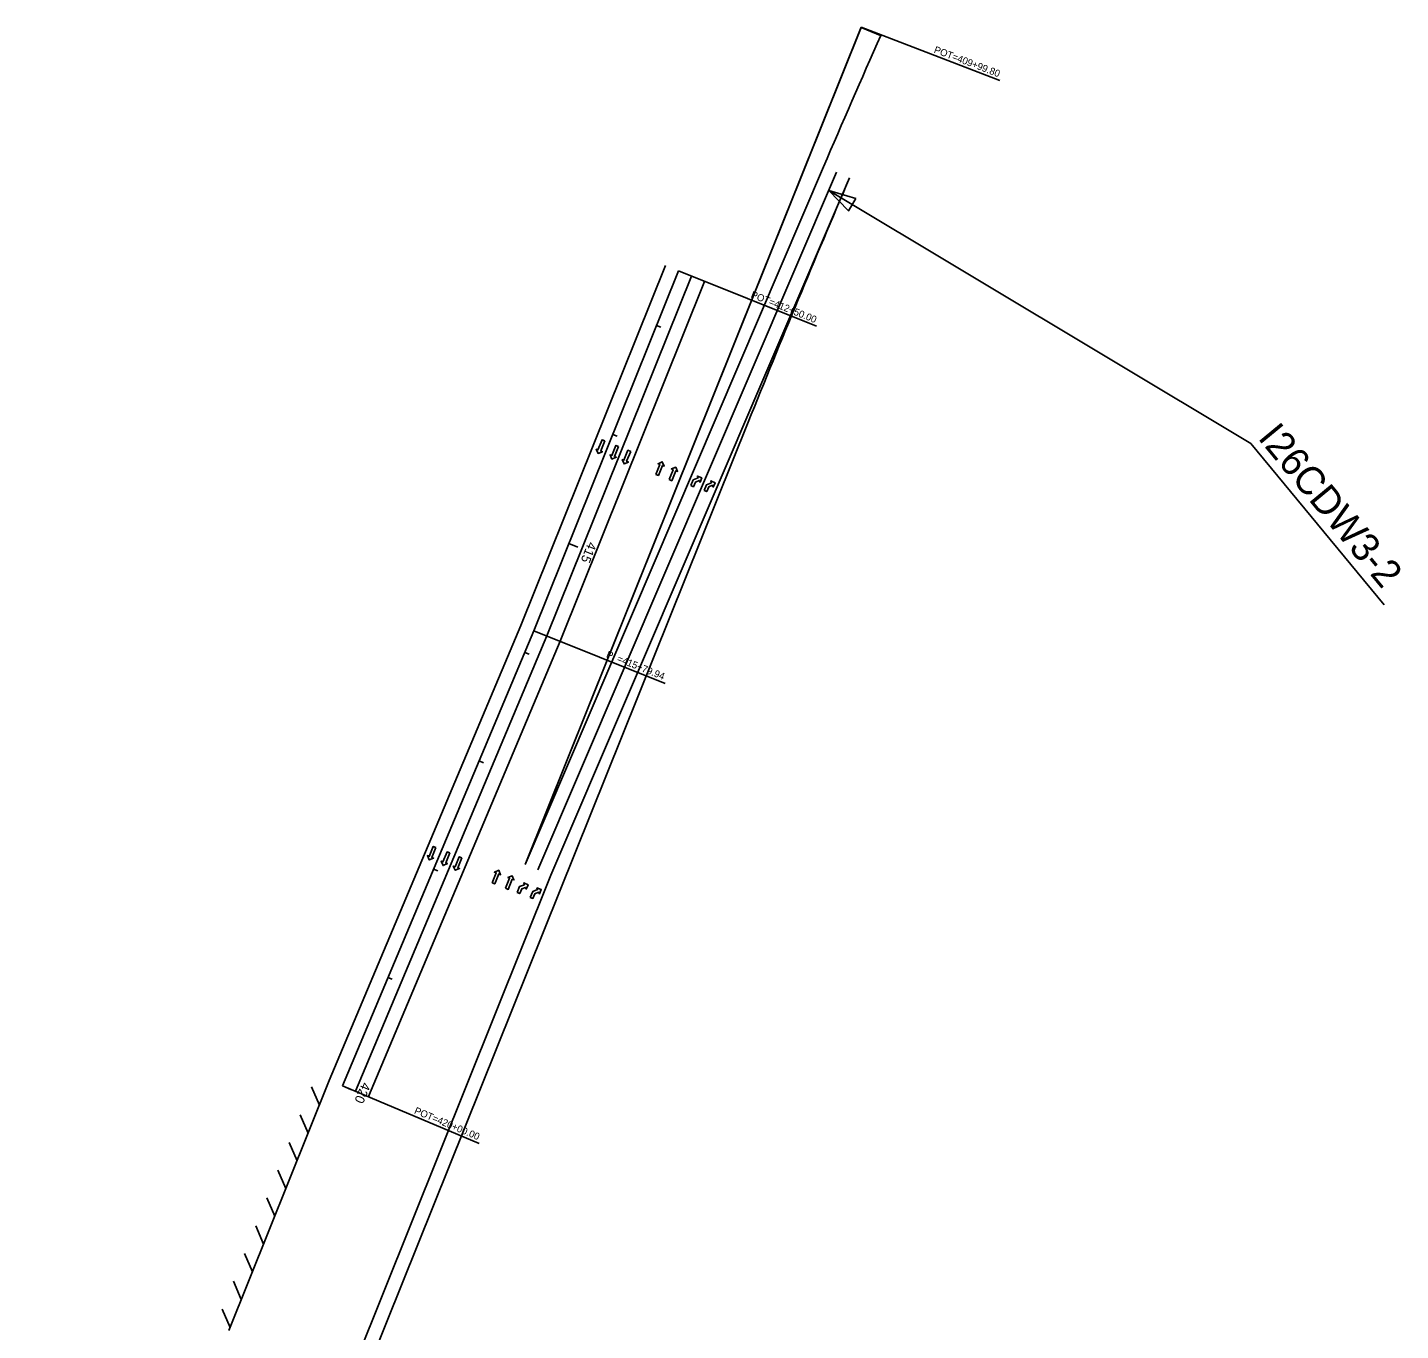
# Model space of a CAD drawing. Extents: x 1966356 to 1974207, y 790684 to 800034.
# Drawn here: x 1967461 to 1968629, y 794637 to 795746 of the extents above; entities that cross this region are included whole.
import ezdxf

# ---------------------------------------------------------------- set-up
doc = ezdxf.new("R2010")
doc.units = 0
for name, color, linetype in [('RD_EX_Pavement_Markings', 7, 'Continuous'), ('RD_HC_Cl', 7, 'Continuous'), ('RD_HC_Data', 7, 'Continuous'), ('RD_HC_Data_Tic', 7, 'Continuous'), ('RD_HC_TX_Sta50', 7, 'Continuous'), ('RD_PD_ALT5_LnLine', 7, 'Continuous'), ('RD_PD_ALT5_TrvlWay', 7, 'Continuous'), ('RD_TX_RoadID', 7, 'Continuous')]:
    doc.layers.add(name, color=color, linetype=linetype)

msp = doc.modelspace()

# ---------------------------------------------------------------- linework, layer by layer
at = {"layer": 'RD_EX_Pavement_Markings'}
for p, q in [((1968003.9, 795543.4), (1967880.9, 795237.2)), ((1968015, 795538.9), (1967892.1, 795232.7)), ((1968026.2, 795534.4), (1967903.2, 795228.3)), ((1968037.3, 795530), (1967914.4, 795223.8))]:
    msp.add_line(p, q, dxfattribs=at)
at = {"layer": 'RD_HC_Cl'}
for p, q in [((1968015, 795538.9), (1967892.1, 795232.7)), ((1967892.1, 795232.7), (1967729.1, 794845.6))]:
    msp.add_line(p, q, dxfattribs=at)
at = {"layer": 'RD_HC_Data'}
for p, q in [((1968170.5, 795746.2), (1968288.6, 795701)), ((1968015, 795538.9), (1968132.4, 795491.8)), ((1967892.1, 795232.7), (1968003.7, 795187.9)), ((1967729.1, 794845.6), (1967845.6, 794796.5))]:
    msp.add_line(p, q, dxfattribs=at)
at = {"layer": 'RD_HC_Data_Tic'}
for p, q in [((1967996.4, 795492.5), (1968000.1, 795491)), ((1967959.1, 795399.7), (1967962.9, 795398.2)), ((1967921.9, 795306.9), (1967929.3, 795303.9)), ((1967884.3, 795214.2), (1967888, 795212.7)), ((1967845.5, 795122.1), (1967849.2, 795120.5)), ((1967806.7, 795029.9), (1967810.4, 795028.4)), ((1967767.9, 794937.8), (1967771.6, 794936.2)), ((1967729.1, 794845.6), (1967736.4, 794842.5))]:
    msp.add_line(p, q, dxfattribs=at)
at = {"layer": 'RD_PD_ALT5_LnLine'}
for p, q in [((1967895.5, 795029.3), (1968149.5, 795622.8)), ((1967892.1, 795232.7), (1967729.1, 794845.6)), ((1967903.2, 795228.3), (1967740.2, 794841.1))]:
    msp.add_line(p, q, dxfattribs=at)
for points in [[(1967952.3, 795394.3), (1967950.1, 795395.2), (1967946.6, 795386.6), (1967945.1, 795387.2), (1967946.7, 795383.6), (1967950.4, 795385.1), (1967948.9, 795385.7)], [(1967964, 795389.5), (1967961.8, 795390.4), (1967958.4, 795381.9), (1967956.9, 795382.5), (1967958.5, 795378.8), (1967962.1, 795380.4), (1967960.6, 795381)], [(1967974.4, 795385.4), (1967972.1, 795386.3), (1967968.7, 795377.8), (1967967.2, 795378.4), (1967968.8, 795374.7), (1967972.5, 795376.3), (1967970.9, 795376.9)], [(1967995.8, 795365.8), (1967998, 795364.9), (1968001.4, 795373.4), (1968002.9, 795372.8), (1968001.3, 795376.5), (1967997.7, 795374.9), (1967999.2, 795374.3)], [(1968007.1, 795361.3), (1968009.4, 795360.4), (1968012.8, 795368.9), (1968014.3, 795368.3), (1968012.7, 795371.9), (1968009, 795370.4), (1968010.5, 795369.8)], [(1968025.6, 795356.2), (1968027.7, 795361.1), (1968031.8, 795362.8), (1968031.2, 795364.3), (1968034.9, 795362.8), (1968033.4, 795359.1), (1968032.8, 795360.6), (1968029.5, 795359.3), (1968027.8, 795355.3)], [(1968036.9, 795352.1), (1968038.9, 795357), (1968043.1, 795358.7), (1968042.5, 795360.2), (1968046.2, 795358.7), (1968044.6, 795355), (1968044, 795356.5), (1968040.8, 795355.2), (1968039.1, 795351.1)], [(1967808.6, 795048.4), (1967806.4, 795049.3), (1967803, 795040.8), (1967801.5, 795041.4), (1967803, 795037.7), (1967806.7, 795039.3), (1967805.2, 795039.9)], [(1967820.4, 795043.7), (1967818.2, 795044.6), (1967814.7, 795036.1), (1967813.2, 795036.7), (1967814.8, 795033), (1967818.5, 795034.6), (1967817, 795035.2)], [(1967830.7, 795039.6), (1967828.5, 795040.4), (1967825.1, 795031.9), (1967823.5, 795032.5), (1967825.1, 795028.9), (1967828.8, 795030.4), (1967827.3, 795031)], [(1967856.6, 795018.2), (1967858.8, 795017.3), (1967862.2, 795025.8), (1967863.7, 795025.2), (1967862.2, 795028.9), (1967858.5, 795027.3), (1967860, 795026.7)], [(1967867.9, 795013.6), (1967870.2, 795012.7), (1967873.6, 795021.3), (1967875.1, 795020.7), (1967873.5, 795024.3), (1967869.9, 795022.8), (1967871.4, 795022.2)], [(1967877.8, 795010), (1967879.8, 795015), (1967884, 795016.7), (1967883.4, 795018.2), (1967887.1, 795016.6), (1967885.5, 795012.9), (1967884.9, 795014.4), (1967881.7, 795013.1), (1967880, 795009.1)], [(1967889, 795005.9), (1967891.1, 795010.8), (1967895.2, 795012.5), (1967894.6, 795014), (1967898.3, 795012.5), (1967896.8, 795008.8), (1967896.1, 795010.3), (1967892.9, 795009), (1967891.2, 795005)]]:
    msp.add_lwpolyline(points, close=True, dxfattribs=at)
at = {"layer": 'RD_PD_ALT5_TrvlWay'}
for p, q in [((1968170.5, 795746.2), (1967884.5, 795034)), ((1968170.4, 795746), (1967884.5, 795034)), ((1968187.1, 795739.3), (1968170.4, 795746)), ((1967884.5, 795034), (1968138.5, 795627.5)), ((1967884.5, 795034), (1968138.5, 795627.5)), ((1967906.6, 795024.8), (1968160.6, 795618.1)), ((1968160.6, 795618.1), (1967906.6, 795024.8)), ((1967472.3, 793911.1), (1968074.4, 795410.3)), ((1967717.9, 794850.1), (1967880.9, 795237.2)), ((1967914.4, 795223.8), (1967751.3, 794836.6)), ((1967906.6, 795024.8), (1967461.2, 793915.6)), ((1967906.6, 795024.8), (1967461.2, 793915.6)), ((1967717.9, 794850.1), (1967632.5, 794637.3)), ((1967702.8, 794844.6), (1967709.5, 794829)), ((1967693.3, 794821), (1967700, 794805.4)), ((1967683.8, 794797.4), (1967690.5, 794781.8)), ((1967674.3, 794773.7), (1967681, 794758.1)), ((1967664.9, 794750.1), (1967671.5, 794734.5)), ((1967655.4, 794726.5), (1967662, 794710.9)), ((1967645.9, 794702.9), (1967652.5, 794687.3)), ((1967636.4, 794679.3), (1967643.1, 794663.7)), ((1967626.9, 794655.6), (1967633.6, 794640))]:
    msp.add_line(p, q, dxfattribs=at)
for radius, start, end in [(10012, 156.13137, 156.82865), (9988, 156.82866, 158.11901)]:
    msp.add_arc((1977342.9, 791688), radius, start, end, dxfattribs=at)
at = {"layer": 'RD_TX_RoadID'}
msp.add_line((1968615.5, 795254.8), (1968502, 795392.2), dxfattribs=at)
msp.add_lwpolyline([(1968502, 795392.2), (1968142.9, 795607.2)], dxfattribs=at)
msp.add_lwpolyline([(1968165.9, 795600.6), (1968142.9, 795607.2), (1968159.6, 795589.9)], close=True, dxfattribs=at)

# ---------------------------------------------------------------- texts
at = {"layer": 'RD_HC_Data'}
for s, rotation, p in [('POT=409+99.80', 339.074, (1968231.9, 795724.8)), ('POT=412+50.00', 338.119, (1968076.1, 795516.5)), ('PI =415+79.94', 338.119, (1967953.1, 795210.4)), ('POT=420+00.00', 337.1642, (1967789.7, 794822.2))]:
    msp.add_text(s, height=6, rotation=rotation, dxfattribs=at).set_placement(p)
at = {"layer": 'RD_HC_TX_Sta50'}
for s, rotation, p in [('415', 248.119, (1967938.4, 795309)), ('420', 247.1642, (1967746.1, 794849.2))]:
    msp.add_text(s, height=8, rotation=rotation, dxfattribs=at).set_placement(p)
at = {"layer": 'RD_TX_RoadID'}
msp.add_text('I26CDW3-2 ', height=24, rotation=309.5517, dxfattribs=at).set_placement((1968507.4, 795396.7))

doc.saveas('drawing.dxf')
